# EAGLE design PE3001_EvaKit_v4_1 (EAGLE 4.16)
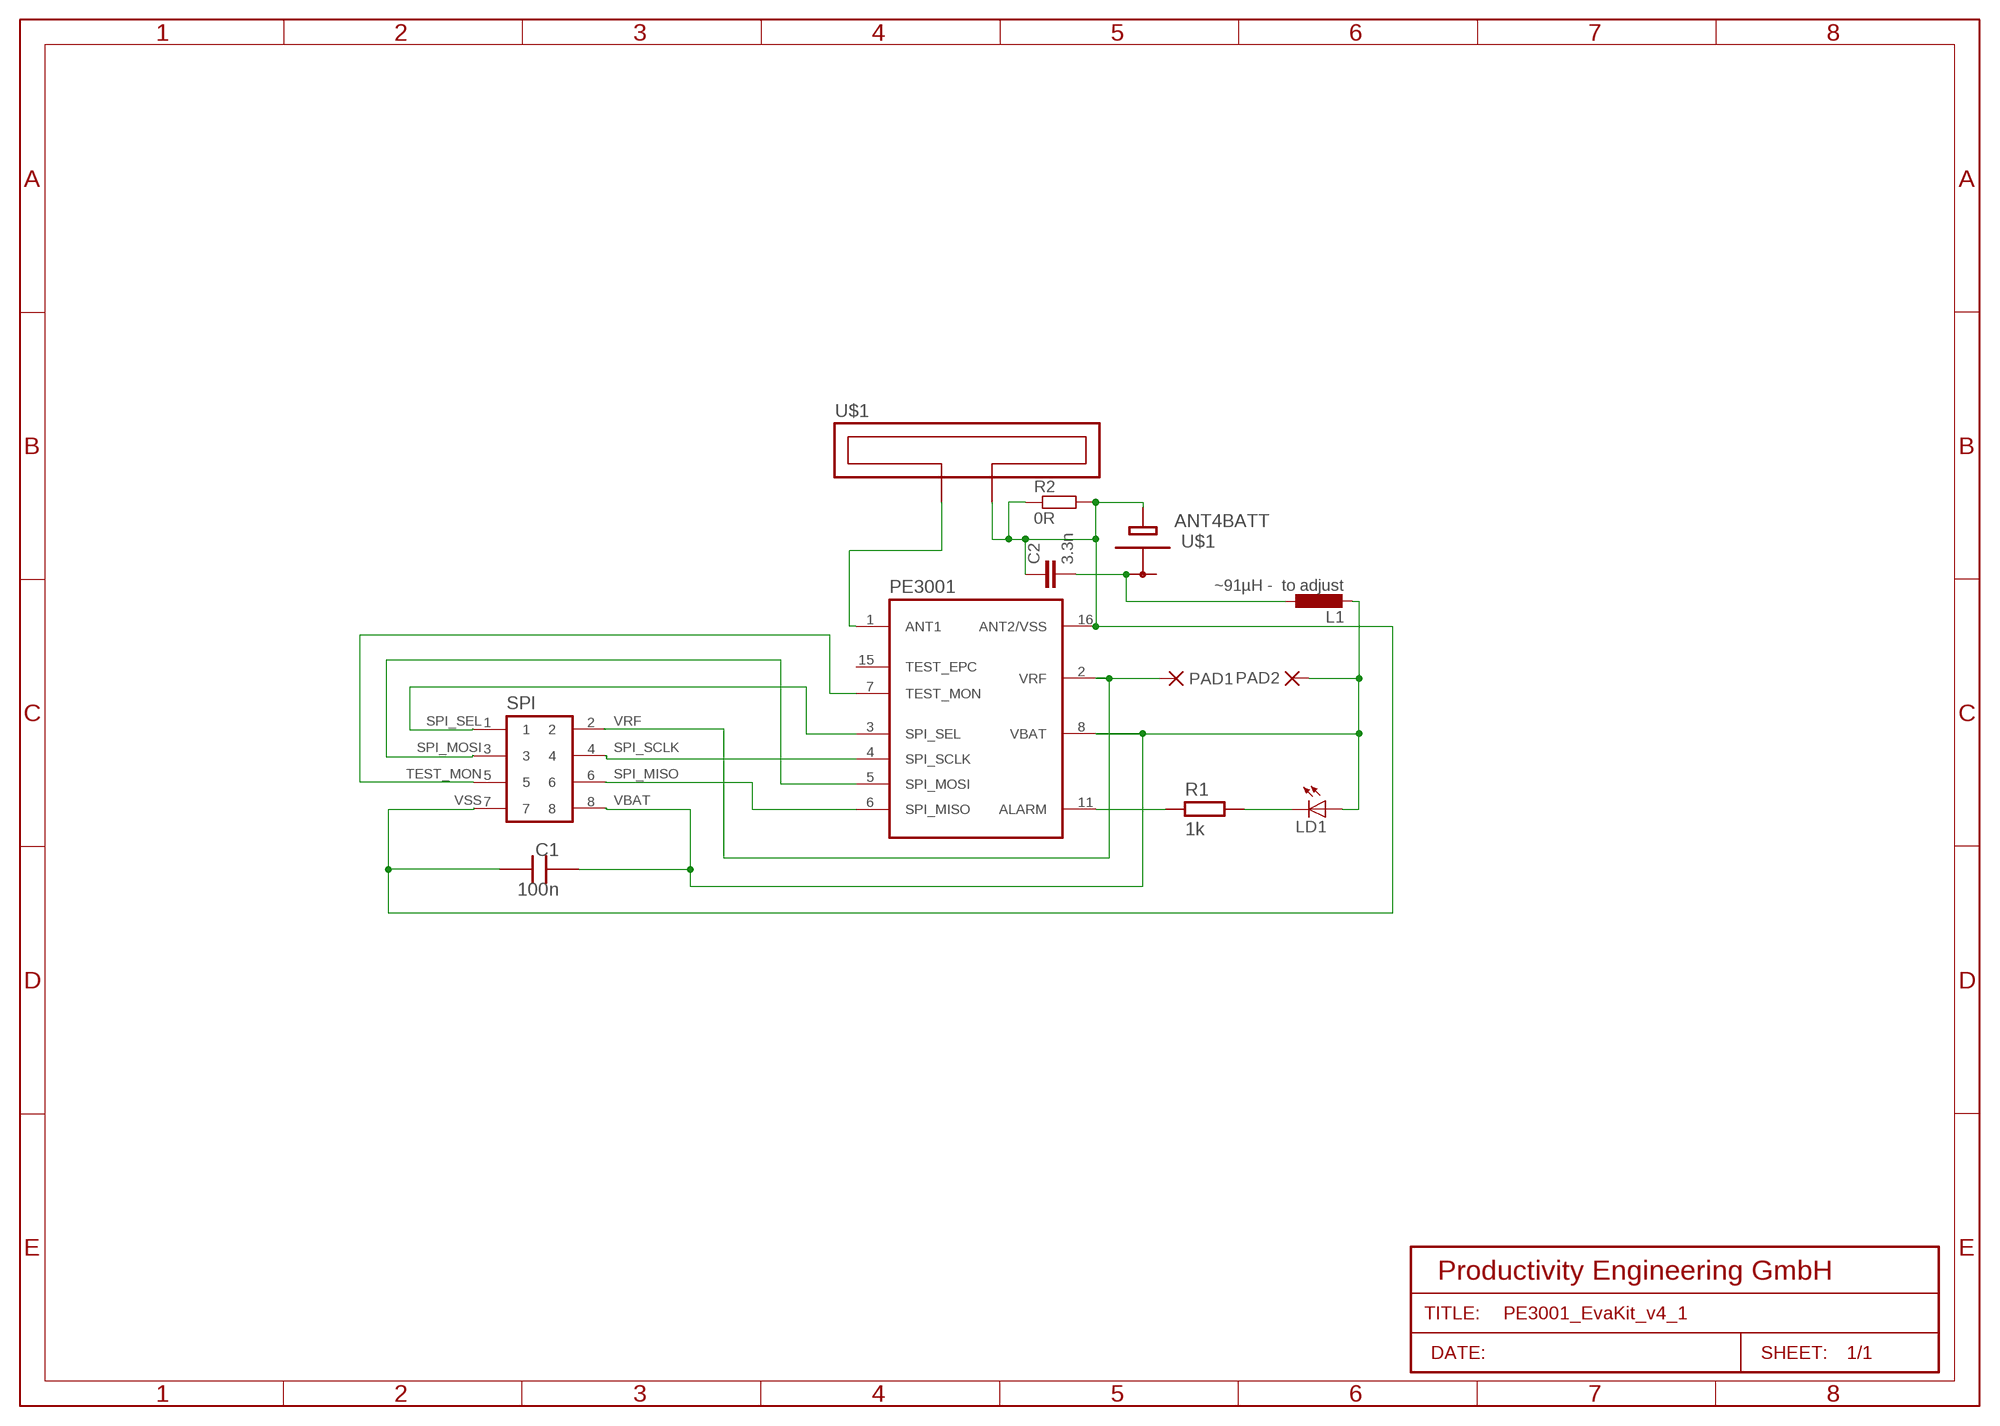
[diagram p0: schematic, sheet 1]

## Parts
C1  100n  CAP  [C0805]
C2  3.3n  C-EUC0402  [C0402]
L1  ~91µH - to adjust  L-EUL4532C  [L4532M]
LD1  LEDCHIPLED_1206  [CHIPLED_1206]
PAD1  PAD-SMD10R  [SMD10R]
PAD2  PAD-SMD10R  [SMD10R]
PE3001  PE3001  [TSSOP16]
R1  1k  RES  [R0805]
R2  0R  R-EU_M1406  [M1406]
SPI  CON  [TMM_2X4]
U$1  ANT4BATT  [PE3001_EVAKIT_V4_1_ANT]

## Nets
ALARM: PE3001.11(ALARM) R1.1
ANT1: PE3001.1(ANT1) U$1.2(ANT1)
N$1: LD1.C R1.2
N$2: C2.2 L1.1 U$1.P$2(P2)
SPI_MISO: PE3001.6(SPI_MISO) SPI.6
SPI_MOSI: PE3001.5(SPI_MOSI) SPI.3
SPI_SCLK: PE3001.4(SPI_SCLK) SPI.4
SPI_SEL: PE3001.3(SPI_SEL) SPI.1
TEST_MON: PE3001.7(TEST_MON) SPI.5
VBAT: C1.1 L1.2 LD1.A PAD2.PAD(P) PE3001.8(VBAT) SPI.8
VRF: PAD1.PAD(P) PE3001.2(VRF) SPI.2
VSS: C1.2 C2.1 PE3001.16(ANT2/VSS) R2.1 R2.2 SPI.7 U$1.1(ANT2) U$1.P$3(N)
Unconnected: PE3001.15(TEST_EPC) U$1.P$1(P1)

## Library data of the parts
C1 = PE3001_EvaKit_v2:CAP
C2 = rcl:C-EU: CAPACITOR, European symbol
L1 = rcl:L-EU: INDUCTOR, European symbol
LD1 = led:LED: LED
PAD1 PAD2 = dpads:PAD: WIRE PAD
PE3001 = PE3001_EvaKit_v2:PE3001
R1 = PE3001_EvaKit_v2:RES
R2 = rcl:R-EU_: RESISTOR, European symbol
SPI = PE3001_EvaKit_v2:CON
U$1 = PE3001_EvaKit_v4:ANT4BATT

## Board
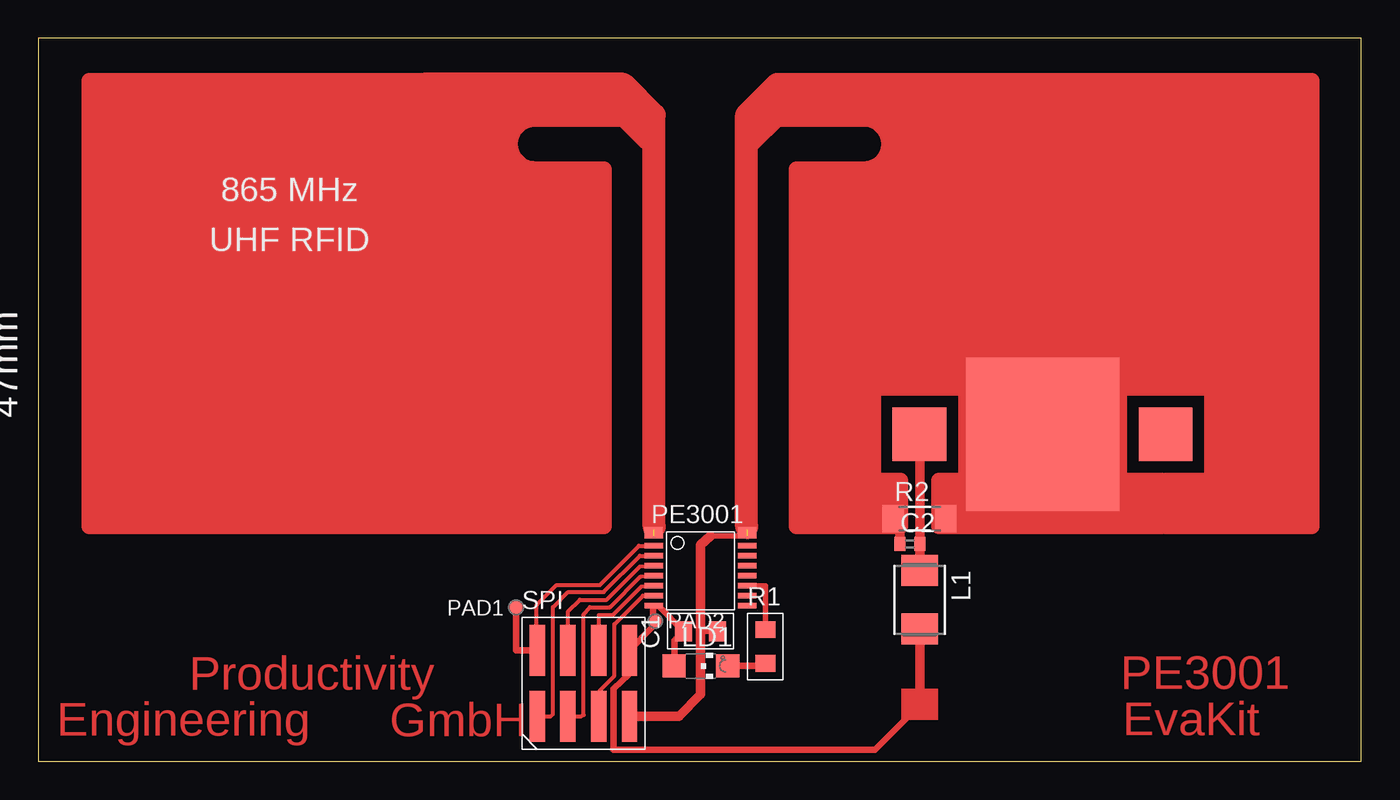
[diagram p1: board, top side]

Size 86 x 47 mm. Coordinates in mm from the lower left corner, seen from the top.
Outline: 0,0 86,0 86,47 0,47 0,0
Copper layers (1*16): Top 0.035mm / dielectric 1.5mm / Bottom 0.035mm
Design rules "PCB-POOL": minimum track width 6mil, minimum drill 12mil, track to track 6mil, track to pad 6mil, pad to pad 6mil, via to via 6mil, smd to smd 6mil, copper to edge 20mil, drill to drill 8mil, minimum pad ring 8mil, minimum via ring 6mil, stop-mask expansion 3mil, vias tented up to drill 0mil, thermal gap 8mil

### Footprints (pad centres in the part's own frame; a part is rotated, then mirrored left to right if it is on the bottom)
C0805 = smd 1.3 x 1.1: 1 0,1.1; 2 0,-1.1
C0402 = smd 0.7 x 0.9: 1 -0.65,0; 2 0.65,0
L4532M = smd 2 x 2.4: 1 -1.9,0; 2 1.9,0
CHIPLED_1206 = smd 1.5 x 1.5: A 0,-1.75; C 0,1.75
SMD10R = smd 1 x 1: PAD 0,0
TSSOP16 = smd 1.2 x 0.36: 1 -3.05,2; 2 -3.05,1.35; 3 -3.05,0.7; 4 -3.05,0.05; 5 -3.05,-0.6; 6 -3.05,-1.25; 7 -3.05,-1.9; 8 -3.05,-2.55; 9 3.05,-2.55; 10 3.05,-1.9; 11 3.05,-1.25; 12 3.05,-0.6; 13 3.05,0.05; 14 3.05,0.7; 15 3.05,1.35; 16 3.05,2
R0805 = smd 1.3 x 1.1: 1 0,1.1; 2 0,-1.1
M1406 = smd 1.4 x 1.8: 1 -1.7,0; 2 1.7,0
TMM_2X4 = smd 1 x 3.3: 1 -3,-2.15; 2 -3,2.15; 3 -1,-2.15; 4 -1,2.15; 5 1,-2.15; 6 1,2.15; 7 3,-2.15; 8 3,2.15
PE3001_EVAKIT_V4_1_ANT = smd 1.2 x 0.36: 1 3.05,-14.7; 2 -3.05,-14.7 | smd 3.5 x 3.5: P$1 30.25,-8.5; P$2 14.25,-8.5 | smd 10 x 10: P$3 22.25,-8.5

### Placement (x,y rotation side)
C1  43.05,8.45 90 top
C2  56.66,14.12 0 top
L1  57.3,10.5 270 top
LD1  43.07,6.19 270 top
PAD1  31.05,10 180 top
PAD2  40.1,9.1 0 top
PE3001  43.05,12.65 0 top
R1  47.26,7.45 0 top
R2  57.29,15.77 0 top
SPI  35.43,5.06 0 top
U$1  43.04,29.76 0 top

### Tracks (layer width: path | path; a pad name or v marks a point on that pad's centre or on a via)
ALARM
  Top 0.36: R1.1 47.26,10.81 47.26,11.41 PE3001.11
ANT1  (1 unrouted)
N$1
  Top 0.406: R1.2 47.26,6.45 47.25,6.45 46.99,6.19 LD1.C
N$2
  Top 0.406: C2.2 | U$1.P$2
  Top 0.61: U$1.P$2 C2.2 L1.1
SPI_MISO
  Top 0.25: SPI.6 36.45,9.5 37.35,9.5 39.2,11.35 PE3001.6
SPI_MOSI
  Top 0.25: SPI.3 35.28,2.91 35.45,3 35.45,9.55 35.85,10 37.15,10 39.15,12 PE3001.5
SPI_SCLK
  Top 0.25: SPI.4 34.45,9.75 35.2,10.5 36.95,10.5 39.1,12.65 PE3001.4
SPI_SEL
  Top 0.25: SPI.1 33.28,2.91 33.45,3.05 33.45,10 34.45,11 36.75,11 39.1,13.35 PE3001.3
TEST_MON
  Top 0.25: SPI.5 36.5,4.6 37.45,5.55 37.45,8.9 39.3,10.75 PE3001.7
VBAT
  Top 0.406: 39.98,10.08 39.94,10.08 | PE3001.8 39.98,10.08 | 39.98,10.08 40.32,10.08 C1.1 41.35,7.85 41.35,6.15 | 41.35,6.15 41.35,6.05 | 41.35,6.15 LD1.A | 39.95,9.05 PAD2.PAD arc4 39.95,9.05 | SPI.8 38.35,7.21 | PE3001.8 39.95,10.1 | 57.3,3.65 54.4,0.75 37.4,0.75 37.4,4.7 38.4,5.65 38.4,7.2 SPI.8 | SPI.8 39.9,8.7 39.95,9.05 | PE3001.8 39.95,10.05 39.95,9.05
  Top 0.61: 57.3,3.65 L1.2
VRF
  Top 0.25: SPI.2 32.4,10.15 33.7,11.45 36.5,11.45 39.05,14 PE3001.2
  Top 0.36: SPI.2 31.45,7.21
  Top 0.406: SPI.2 32.5,7.2 | SPI.2 | PAD1.PAD 31.05,7.2 SPI.2
VSS  (1 unrouted)
  Top 0.36: 43.7,14.65 PE3001.16
  Top 0.406: C1.2 44.13,8.47 43.05,8.45 | PE3001.16 46.1,41.35 48,43.25 59.35,43.25 65.3,37.3 65.3,27.95 | 65.3,27.95 65.3,21.35 | 65.3,21.35 65.3,21.1 65.29,21.1 U$1.P$3 65.29,21.35 65.3,21.35 | 65.3,27.95 52.9,27.95 52.9,15.8 56.05,15.8 56.01,15.76 56,15.75 55.6,15.75 R2.1 | R2.2 59.72,15.77 65.3,21.35
  Top 0.61: 43.7,14.65 43.05,14.05 43.05,8.45 43.05,4.35 41.65,2.9 arc-1 SPI.7 | 56.01,15.76 C2.1
(copper drawn outside any net)
  shapes: Top area x1

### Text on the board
Top: Productivity | PE3001 | Engineering | GmbH | EvaKit
tNames: 86mm | 47mm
